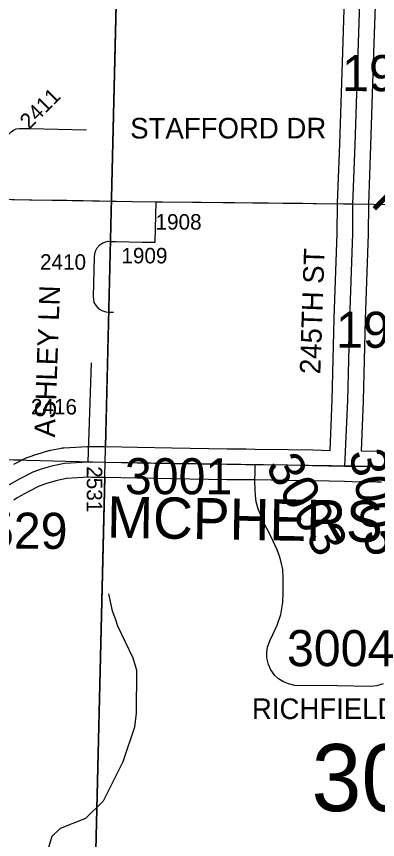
# Model space of a CAD drawing. Extents: x -132.8 to -73.3, y -60 to -26.
# Drawn here: x -116.074 to -115.373, y -49.227 to -47.631 of the extents above; entities that cross this region are included whole.
import ezdxf

# ---------------------------------------------------------------- set-up
doc = ezdxf.new("R2010")
doc.units = 0
for name, color, linetype in [('tdCoHydroRiver', 7, 'Continuous'), ('tdCoPrimary', 7, 'Continuous'), ('tdCoPriNonDiv', 7, 'Continuous'), ('tdCoPriNonDivCL', 7, 'Continuous'), ('tdCoSecRdNmbr', 7, 'Continuous'), ('tdCoSecRdTxt', 7, 'Continuous'), ('tdCoSecRteBand', 7, 'Continuous'), ('tdCoSecRteCL', 7, 'Continuous'), ('tdCoSectLine', 7, 'Continuous'), ('tdCoSectLinePart', 7, 'Continuous'), ('tdCoSectNmbr', 7, 'Continuous'), ('tdCoSurfAsphalt', 7, 'Continuous'), ('tdCoSurfAsphaltUnbanded', 7, 'Continuous'), ('tdCoSurfBitum', 7, 'Continuous'), ('tdCoSurfConcUnbanded', 7, 'Continuous'), ('tdCoSurfGravel', 7, 'Continuous'), ('tdCoTwpBndry', 7, 'Continuous'), ('tdCoTwpBndryShd', 7, 'Continuous'), ('tdStHwyPriRefPost1', 7, 'Continuous')]:
    doc.layers.add(name, color=color, linetype=linetype)

msp = doc.modelspace()

# ---------------------------------------------------------------- linework, layer by layer
at = {"layer": 'tdCoHydroRiver'}
msp.add_lwpolyline([(-115.8954, -48.7503), (-115.8883, -48.7836), (-115.8824, -48.7979), (-115.878, -48.8123), (-115.848, -48.8745), (-115.8408, -48.8984), (-115.8413, -48.982), (-115.8451, -49.0087), (-115.8674, -49.076), (-115.9056, -49.1523), (-115.9396, -49.1862), (-115.989, -49.2054), (-116.0052, -49.2208), (-116.0138, -49.2489)], dxfattribs=at)
at = {"layer": 'tdCoPrimary'}
msp.add_line((-115.5849, -47.9922), (-115.5192, -47.993), dxfattribs=at)
msp.add_line((-115.5849, -47.9922), (-115.5192, -47.993), dxfattribs=at)
for points in [[(-116.1352, -47.9846), (-116.0784, -47.9856), (-116.0484, -47.9861)], [(-116.1352, -47.9846), (-116.0784, -47.9856), (-116.0484, -47.9861)], [(-116.0784, -47.9856), (-116.0484, -47.9861), (-115.976, -47.9873), (-115.849, -47.9896), (-115.8028, -47.99), (-115.7154, -47.9908), (-115.5849, -47.9922), (-115.5192, -47.993), (-115.4915, -47.9933), (-115.421, -47.994), (-115.381, -47.9945), (-115.253, -47.9967)], [(-116.0484, -47.9861), (-115.976, -47.9873), (-115.849, -47.9896), (-115.8028, -47.99), (-115.7154, -47.9908), (-115.5849, -47.9922)], [(-116.0484, -47.9861), (-115.976, -47.9873), (-115.849, -47.9896), (-115.8028, -47.99), (-115.7154, -47.9908), (-115.5849, -47.9922)], [(-115.5192, -47.993), (-115.4915, -47.9933), (-115.421, -47.994), (-115.381, -47.9945), (-115.253, -47.9967)], [(-115.5192, -47.993), (-115.4915, -47.9933), (-115.421, -47.994), (-115.381, -47.9945), (-115.253, -47.9967)]]:
    msp.add_lwpolyline(points, dxfattribs=at)
at = {"layer": 'tdCoPriNonDiv'}
msp.add_lwpolyline([(-118.6189, -48.0711), (-118.3293, -48.0635), (-117.7562, -48.0537), (-117.6521, -48.0512), (-117.4593, -48.0386), (-117.0314, -48.0073), (-116.8551, -47.9938), (-116.6524, -47.9799), (-116.5495, -47.978), (-115.8494, -47.9896), (-115.3814, -47.9945), (-115.064, -47.9989)], dxfattribs=at)
at = {"layer": 'tdCoPriNonDivCL'}
msp.add_lwpolyline([(-116.0788, -47.9856), (-116.0488, -47.9861), (-115.9764, -47.9873), (-115.8494, -47.9896), (-115.8032, -47.99), (-115.7158, -47.9908), (-115.5853, -47.9922), (-115.5196, -47.993), (-115.4918, -47.9933), (-115.4214, -47.994), (-115.3814, -47.9945), (-115.2534, -47.9967)], dxfattribs=at)
msp.add_lwpolyline([(-116.0788, -47.9856), (-116.0488, -47.9861), (-115.9764, -47.9873), (-115.8494, -47.9896), (-115.8032, -47.99), (-115.7158, -47.9908), (-115.5853, -47.9922), (-115.5196, -47.993), (-115.4918, -47.9933), (-115.4214, -47.994), (-115.3814, -47.9945), (-115.2534, -47.9967)], dxfattribs=at)
at = {"layer": 'tdCoSecRteBand'}
for points in [[(-116.0788, -48.4991), (-116.0548, -48.4869), (-116.0529, -48.4859), (-116.0508, -48.4852), (-116.0346, -48.4797), (-116.0341, -48.4796), (-116.0336, -48.4794), (-116.0109, -48.4726), (-116.0095, -48.4722), (-116.0081, -48.4719), (-115.9862, -48.4676), (-115.9842, -48.4672), (-115.9822, -48.4671), (-115.9363, -48.4644), (-115.9349, -48.4643), (-115.9334, -48.4644), (-115.9256, -48.4647), (-115.901, -48.4649), (-115.9009, -48.4649), (-115.9007, -48.4649), (-115.8389, -48.4661), (-115.8388, -48.4661), (-115.8388, -48.4661), (-115.7723, -48.4674), (-115.6651, -48.4691), (-115.6284, -48.4694), (-115.6284, -48.4694), (-115.6283, -48.4694), (-115.6105, -48.4696), (-115.547, -48.4704), (-115.5468, -48.4704), (-115.5467, -48.4704), (-115.4991, -48.4714), (-115.4991, -48.4714), (-115.4991, -48.4714), (-115.4653, -48.4721), (-115.4612, -48.3742), (-115.4573, -48.2168), (-115.4573, -48.2167), (-115.4573, -48.2165), (-115.4514, -48.0512), (-115.451, -47.9939), (-115.451, -47.9934), (-115.451, -47.9929), (-115.4467, -47.8787), (-115.441, -47.6997), (-115.441, -47.6997), (-115.441, -47.6997), (-115.4356, -47.5349)], [(-115.3503, -47.5364), (-115.3756, -47.5359), (-115.381, -47.7017), (-115.3867, -47.8807), (-115.3867, -47.8808), (-115.3867, -47.8809), (-115.391, -47.9947), (-115.3914, -48.052), (-115.3914, -48.0525), (-115.3914, -48.0529), (-115.3973, -48.2185), (-115.4013, -48.3759), (-115.4013, -48.3762), (-115.4013, -48.3764), (-115.4053, -48.4732), (-115.3741, -48.4736), (-115.374, -48.4736), (-115.374, -48.4736), (-115.3649, -48.4738)], [(-115.366, -48.5338), (-115.375, -48.5336), (-115.4072, -48.5332), (-115.4072, -48.5334), (-115.4078, -48.5333), (-115.4078, -48.5339), (-115.4375, -48.5327), (-115.4672, -48.5321), (-115.5004, -48.5314), (-115.5478, -48.5304), (-115.6113, -48.5296), (-115.629, -48.5293), (-115.6656, -48.5291), (-115.6658, -48.5291), (-115.6659, -48.5291), (-115.7733, -48.5274), (-115.7734, -48.5274), (-115.7735, -48.5274), (-115.84, -48.526), (-115.9017, -48.5249), (-115.9265, -48.5247), (-115.927, -48.5247), (-115.9274, -48.5247), (-115.9343, -48.5244), (-115.9766, -48.5269), (-115.9951, -48.5305), (-116.0158, -48.5367), (-116.0295, -48.5414), (-116.0511, -48.5523), (-116.0723, -48.5642), (-116.0792, -48.5684)]]:
    msp.add_lwpolyline(points, dxfattribs=at)
at = {"layer": 'tdCoSecRteCL'}
msp.add_line((-115.9346, -48.4944), (-115.9283, -48.3024), dxfattribs=at)
for points in [[(-115.4365, -48.5027), (-115.4312, -48.3752), (-115.4273, -48.2176), (-115.4214, -48.0519), (-115.421, -47.994), (-115.4167, -47.8797), (-115.411, -47.7007), (-115.4054, -47.5271), (-115.4054, -47.5054)], [(-116.1305, -47.8793), (-116.1249, -47.8799), (-116.1183, -47.8799), (-116.1114, -47.8789), (-116.1047, -47.8764), (-116.0985, -47.8727), (-116.0936, -47.8661), (-116.0894, -47.8594), (-116.0842, -47.8547), (-116.0793, -47.8513), (-116.0741, -47.849), (-116.068, -47.8481), (-116.0477, -47.8481), (-115.9378, -47.8508)], [(-115.8853, -48.2049), (-115.8957, -48.2049), (-115.8999, -48.2043), (-115.9075, -48.2018), (-115.9131, -48.1984), (-115.9186, -48.1918), (-115.9229, -48.1856), (-115.924, -48.1797), (-115.9246, -48.1738), (-115.9223, -48.0967), (-115.922, -48.0917), (-115.9206, -48.0858), (-115.9173, -48.0794), (-115.9122, -48.0738), (-115.9063, -48.0699), (-115.9005, -48.0676), (-115.8957, -48.0668), (-115.8911, -48.0669), (-115.8808, -48.0671), (-115.8301, -48.0682), (-115.8049, -48.0682), (-115.8028, -47.99)], [(-116.2837, -48.689), (-116.2759, -48.6857), (-116.2575, -48.676), (-116.2378, -48.6643), (-116.216, -48.6482), (-116.2044, -48.638), (-116.1875, -48.6224), (-116.1657, -48.6035), (-116.1451, -48.5852), (-116.1232, -48.5656), (-116.0965, -48.5438), (-116.0874, -48.5383), (-116.0653, -48.5259), (-116.0412, -48.5137), (-116.025, -48.5081), (-116.0023, -48.5014), (-115.9804, -48.4971), (-115.9346, -48.4944)], [(-115.9346, -48.4944), (-115.9263, -48.4947), (-115.9013, -48.4949), (-115.8394, -48.496), (-115.7729, -48.4974), (-115.6654, -48.4991), (-115.6287, -48.4993), (-115.6109, -48.4996)], [(-115.3622, -48.9246), (-115.375, -48.9285), (-115.3871, -48.9298), (-115.4517, -48.9288), (-115.5336, -48.9278), (-115.5459, -48.9251), (-115.5558, -48.9209), (-115.5654, -48.9152), (-115.5726, -48.9088), (-115.5802, -48.898), (-115.5851, -48.8876), (-115.5878, -48.8743), (-115.5878, -48.8632), (-115.5866, -48.8536), (-115.5822, -48.8415), (-115.5763, -48.8292), (-115.5679, -48.8114), (-115.5609, -48.7904), (-115.557, -48.7672), (-115.5563, -48.747), (-115.5563, -48.7184), (-115.5572, -48.7034), (-115.5602, -48.6888), (-115.5634, -48.6772), (-115.5681, -48.6652), (-115.5812, -48.6375), (-115.5952, -48.6099), (-115.6048, -48.5857), (-115.6088, -48.5717), (-115.6103, -48.5599), (-115.611, -48.5483), (-115.6112, -48.5312), (-115.6108, -48.514), (-115.6109, -48.4996)], [(-115.6109, -48.4996), (-115.5473, -48.5004), (-115.4998, -48.5014), (-115.4365, -48.5027)], [(-115.4365, -48.5027), (-115.4357, -48.5027), (-115.3745, -48.5036), (-115.3654, -48.5038)]]:
    msp.add_lwpolyline(points, dxfattribs=at)
at = {"layer": 'tdCoSectLine'}
for points in [[(-115.9017, -48.4949), (-115.8779, -47.4977)], [(-116.8881, -48.4697), (-115.9017, -48.4949)], [(-115.9254, -49.4919), (-115.9017, -48.4949)], [(-115.9017, -48.4949), (-114.937, -48.5091)]]:
    msp.add_lwpolyline(points, dxfattribs=at)
at = {"layer": 'tdCoSectLinePart'}
for points in [[(-115.8908, -48.0369), (-115.8786, -47.5277)], [(-115.894, -48.1746), (-115.8922, -48.0968)], [(-115.901, -48.4649), (-115.8955, -48.2348)], [(-116.3054, -48.4846), (-116.0624, -48.4908)], [(-115.9247, -49.4617), (-115.9024, -48.5249)]]:
    msp.add_lwpolyline(points, dxfattribs=at)
at = {"layer": 'tdCoSurfAsphalt'}
msp.add_lwpolyline([(-116.0874, -48.5383), (-116.0653, -48.5259), (-116.0412, -48.5137), (-116.025, -48.5081), (-116.0023, -48.5014), (-115.9804, -48.4971), (-115.9346, -48.4944), (-115.9263, -48.4947), (-115.9013, -48.4949), (-115.8394, -48.496), (-115.7729, -48.4974), (-115.6654, -48.4991), (-115.6287, -48.4993), (-115.6109, -48.4996), (-115.5473, -48.5004), (-115.4998, -48.5014), (-115.4365, -48.5027), (-115.4357, -48.5027), (-115.3745, -48.5036), (-115.3654, -48.5038)], dxfattribs=at)
at = {"layer": 'tdCoSurfAsphaltUnbanded'}
msp.add_lwpolyline([(-116.1305, -47.8793), (-116.1249, -47.8799), (-116.1183, -47.8799), (-116.1114, -47.8789), (-116.1047, -47.8764), (-116.0985, -47.8727), (-116.0936, -47.8661), (-116.0894, -47.8594), (-116.0842, -47.8547), (-116.0793, -47.8513), (-116.0741, -47.849), (-116.068, -47.8481), (-116.0477, -47.8481), (-115.9378, -47.8508)], dxfattribs=at)
at = {"layer": 'tdCoSurfBitum'}
msp.add_lwpolyline([(-115.4365, -48.5027), (-115.4312, -48.3752), (-115.4273, -48.2176), (-115.4214, -48.0519), (-115.421, -47.994)], dxfattribs=at)
at = {"layer": 'tdCoSurfConcUnbanded'}
msp.add_line((-115.9346, -48.4944), (-115.9283, -48.3024), dxfattribs=at)
for points in [[(-115.8853, -48.2049), (-115.8957, -48.2049), (-115.8999, -48.2043), (-115.9075, -48.2018), (-115.9131, -48.1984), (-115.9186, -48.1918), (-115.9229, -48.1856), (-115.924, -48.1797), (-115.9246, -48.1738), (-115.9223, -48.0967), (-115.922, -48.0917), (-115.9206, -48.0858), (-115.9173, -48.0794), (-115.9122, -48.0738), (-115.9063, -48.0699), (-115.9005, -48.0676), (-115.8957, -48.0668), (-115.8911, -48.0669), (-115.8808, -48.0671), (-115.8301, -48.0682), (-115.8049, -48.0682), (-115.8028, -47.99)], [(-115.3622, -48.9246), (-115.375, -48.9285), (-115.3871, -48.9298), (-115.4517, -48.9288), (-115.5336, -48.9278), (-115.5459, -48.9251), (-115.5558, -48.9209), (-115.5654, -48.9152), (-115.5726, -48.9088), (-115.5802, -48.898), (-115.5851, -48.8876), (-115.5878, -48.8743), (-115.5878, -48.8632), (-115.5866, -48.8536), (-115.5822, -48.8415), (-115.5763, -48.8292), (-115.5679, -48.8114), (-115.5609, -48.7904), (-115.557, -48.7672), (-115.5563, -48.747), (-115.5563, -48.7184), (-115.5572, -48.7034), (-115.5602, -48.6888), (-115.5634, -48.6772), (-115.5681, -48.6652), (-115.5812, -48.6375), (-115.5952, -48.6099), (-115.6048, -48.5857), (-115.6088, -48.5717), (-115.6103, -48.5599), (-115.611, -48.5483), (-115.6112, -48.5312), (-115.6108, -48.514), (-115.6109, -48.4996)]]:
    msp.add_lwpolyline(points, dxfattribs=at)
at = {"layer": 'tdCoSurfGravel'}
msp.add_lwpolyline([(-115.421, -47.994), (-115.4167, -47.8797), (-115.411, -47.7007), (-115.4054, -47.5271), (-115.4054, -47.5054), (-115.4054, -47.4945), (-115.4068, -47.4741), (-115.411, -47.4292), (-115.4123, -47.403), (-115.4125, -47.3739), (-115.4098, -47.3335), (-115.4046, -47.294), (-115.4014, -47.264), (-115.398, -47.2299), (-115.3945, -47.1828), (-115.3888, -47.0418), (-115.3829, -46.8605), (-115.3765, -46.6908), (-115.3708, -46.5291), (-115.3706, -46.522)], dxfattribs=at)
at = {"layer": 'tdCoTwpBndry'}
for points in [[(-115.8786, -47.5277), (-115.901, -48.4649)], [(-115.9024, -48.5249), (-115.9247, -49.4619)]]:
    msp.add_lwpolyline(points, dxfattribs=at)
at = {"layer": 'tdCoTwpBndryShd'}
msp.add_lwpolyline([(-116.128, -56.4384), (-116.0982, -55.4391), (-116.0724, -54.4424), (-116.042, -53.4425), (-116.0101, -52.4492), (-115.9802, -51.4416), (-115.9494, -50.483), (-115.9254, -49.4919), (-115.9017, -48.4949), (-115.8779, -47.4977), (-115.834, -46.4945), (-115.8159, -45.5058), (-115.7834, -44.5349), (-115.7494, -43.5344), (-115.7226, -42.5378), (-115.6969, -41.5376), (-115.6667, -40.5277)], dxfattribs=at)

# ---------------------------------------------------------------- texts
at = {"layer": 'tdCoSecRdNmbr'}
for s, height, rotation, p in [('1904', 0.07, 359.9131, (-115.4421, -47.7756)), ('2411', 0.03, 44.9125, (-116.0493, -47.8511)), ('1908', 0.03, 359.9126, (-115.804, -48.044)), ('1909', 0.03, 359.9126, (-115.8702, -48.1095)), ('2410', 0.03, 359.9126, (-116.0281, -48.1218)), ('1906', 0.07, 359.9131, (-115.4539, -48.2732)), ('2416', 0.03, 359.9126, (-116.0457, -48.4025)), ('3003', 0.07, 299.9131, (-115.5921, -48.5031)), ('3005', 0.07, 279.9131, (-115.4281, -48.4755)), ('3001', 0.07, 359.9128, (-115.8635, -48.5571)), ('2531', 0.03, 269.9126, (-115.9373, -48.5029)), ('2529', 0.07, 359.7179, (-116.1832, -48.6623)), ('3004', 0.07, 359.9128, (-115.5491, -48.8905))]:
    msp.add_text(s, height=height, rotation=rotation, dxfattribs=at).set_placement(p)
at = {"layer": 'tdCoSecRdTxt'}
for s, height, rotation, p in [('STAFFORD DR', 0.04, 0.0242, (-115.8532, -47.8675)), ('245TH ST', 0.04, 88.0076, (-115.4844, -48.325)), ('ASHLEY LN', 0.04, 88.0076, (-115.9994, -48.4472)), ('MCPHERSON AVE', 0.08, 359.0441, (-115.8986, -48.6413)), ('RICHFIELD LP', 0.04, 0.05, (-115.617, -48.9932))]:
    msp.add_text(s, height=height, rotation=rotation, dxfattribs=at).set_placement(p)
at = {"layer": 'tdCoSectNmbr'}
msp.add_text('30', height=0.13, rotation=359.913, dxfattribs=at).set_placement((-115.5014, -49.1716))
at = {"layer": 'tdStHwyPriRefPost1'}
msp.add_text('‒‒11', height=0.1, rotation=45, dxfattribs=at).set_placement((-115.3539, -48.0298))

doc.saveas('drawing.dxf')
